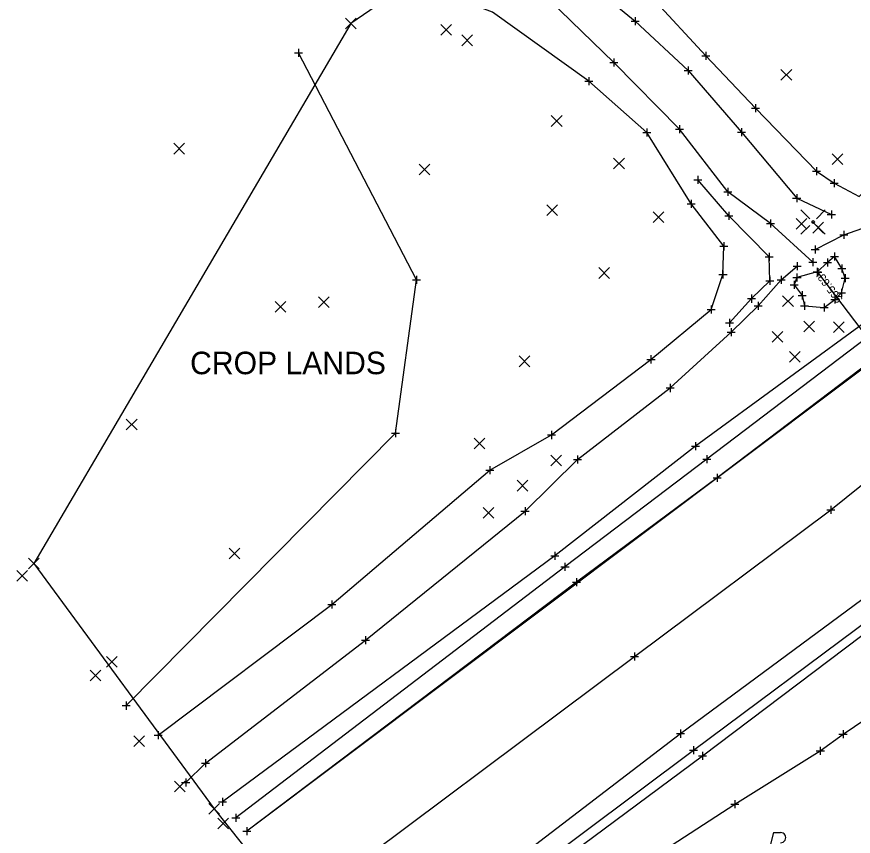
# Model space of a CAD drawing. Extents: x 120332 to 120776, y 463407 to 463745.
# Drawn here: x 120357.5 to 120461.5, y 463500.9 to 463602.7 of the extents above; entities that cross this region are included whole.
import ezdxf

# ---------------------------------------------------------------- set-up
doc = ezdxf.new("R2010")
doc.units = 0
for name, color, linetype in [('Default', 7, 'Continuous'), ('DR_X_Storm_Sewer', 7, 'Continuous'), ('DV_X_Property_Line', 7, 'Continuous'), ('DV_X_Section_VMS_Line', 7, 'Continuous'), ('GE_X_Alignment', 7, 'Continuous'), ('GE_X_Alignment_100_Bearings', 7, 'Continuous'), ('GE_X_Alignment_100_Cardinal_Points', 7, 'Continuous'), ('GE_X_Alignment_100_Distances', 7, 'Continuous'), ('GE_X_Alignment_100_Stations', 7, 'Continuous'), ('RD_X_RR_Cells', 7, 'Continuous'), ('RW_X_Esmt_SH', 7, 'Continuous'), ('SC_Scratch1', 7, 'Continuous'), ('SV_P_Control_Cells_Set', 7, 'Continuous'), ('SV_P_Mon_Cells_Set', 7, 'Continuous'), ('SV_X_Break_Lines', 7, 'Continuous'), ('SV_X_Mon_Cells_Found', 7, 'Continuous'), ('SV_X_Random_Point', 7, 'Continuous'), ('SV_X_Terrain_Boundary', 7, 'Continuous'), ('SV_X_Void_Area', 7, 'Continuous')]:
    doc.layers.add(name, color=color, linetype=linetype)

msp = doc.modelspace()

# ---------------------------------------------------------------- linework, layer by layer
at = {"layer": 'DR_X_Storm_Sewer'}
msp.add_line((120487.84, 463530.38), (120457.07, 463571.01), dxfattribs=at)
at = {"layer": 'DV_X_Property_Line'}
for p, q in [((120456.57, 463571.01), (120457.57, 463571.01)), ((120457.07, 463571.51), (120457.07, 463570.51)), ((120457.07, 463571.01), (120457.07, 463571.01))]:
    msp.add_line(p, q, dxfattribs=at)
at = {"layer": 'DV_X_Section_VMS_Line'}
for p, q in [((120454.98, 463578.73), (120456.07, 463577.64)), ((120456.9, 463577.64), (120458, 463578.73)), ((120454.98, 463575.71), (120456.07, 463576.81)), ((120456.9, 463576.81), (120458, 463575.71))]:
    msp.add_line(p, q, dxfattribs=at)
msp.add_circle((120456.49, 463577.23), 0.17, dxfattribs=at)
at = {"layer": 'GE_X_Alignment'}
for points in [[(120543.45, 463625.61), (120502.74, 463595.17), (120482.09, 463579.11), (120464.32, 463565.8), (120441.86, 463549.38), (120424.38, 463535.76), (120383.06, 463505.19)], [(120400.78, 463479.74), (120442.74, 463510.89), (120464.41, 463527.27), (120481.24, 463539.36), (120504.94, 463557.9), (120520.74, 463569.69), (120562.77, 463600.78)]]:
    msp.add_lwpolyline(points, dxfattribs=at)
at = {"layer": 'GE_X_Alignment_100_Bearings'}
for points in [[(120544.78, 463624.2), (120504.28, 463593.4), (120483.22, 463577.47), (120465.62, 463564.72), (120443.3, 463547.76), (120425.65, 463534.4), (120384.72, 463503.19)], [(120400.11, 463480.54), (120441.64, 463511.61), (120463.87, 463528.17), (120480.16, 463540.69), (120504.52, 463558.73), (120520.21, 463570.42), (120561.99, 463601.9)]]:
    msp.add_lwpolyline(points, dxfattribs=at)
at = {"layer": 'GE_X_Alignment_100_Cardinal_Points'}
for points in [[(120546.27, 463622.13), (120505.75, 463591.54), (120484.55, 463575.45), (120386.09, 463501.54)], [(120392.05, 463491.7), (120434.29, 463523.26), (120458.68, 463541.48), (120471.62, 463551.86), (120496.01, 463569.76), (120511.36, 463581.53), (120553.61, 463612.98)], [(120399.18, 463482.46), (120440.01, 463513.66), (120462.57, 463530.32), (120478.53, 463542.4), (120503.14, 463560.74), (120518.65, 463572.53), (120560.39, 463604.03)]]:
    msp.add_lwpolyline(points, dxfattribs=at)
at = {"layer": 'GE_X_Alignment_100_Distances'}
msp.add_lwpolyline([(120392.05, 463491.7), (120434.29, 463523.26), (120458.68, 463541.48), (120471.62, 463551.86), (120496.01, 463569.76), (120511.36, 463581.53), (120553.61, 463612.98)], dxfattribs=at)
at = {"layer": 'GE_X_Alignment_100_Stations'}
for points in [[(120546.27, 463622.13), (120505.75, 463591.54), (120484.55, 463575.45), (120467.37, 463562.71), (120444.55, 463545.45), (120427.07, 463532.49), (120386.09, 463501.54)], [(120399.18, 463482.46), (120440.01, 463513.66), (120462.57, 463530.32), (120478.53, 463542.4), (120503.14, 463560.74), (120518.65, 463572.53), (120560.39, 463604.03)]]:
    msp.add_lwpolyline(points, dxfattribs=at)
at = {"layer": 'RD_X_RR_Cells'}
for points in [[(120421.56, 463619.93), (120426.3, 463612.62), (120436.47, 463605.12), (120443.17, 463597.87), (120449.32, 463591.39), (120456.91, 463583.55), (120459.12, 463582.05), (120462.23, 463580.42), (120466.75, 463584.83), (120476.93, 463591.15), (120482.16, 463596.63), (120497.16, 463604.58), (120521.1, 463620.25), (120539.56, 463634.42)], [(120375.09, 463513.46), (120396.65, 463529.7), (120416.31, 463546.41), (120423.97, 463550.77), (120436.34, 463560.17), (120443.81, 463566.35), (120445.29, 463570.72), (120445.41, 463574.22), (120441.35, 463579.5), (120435.84, 463588.34), (120428.62, 463594.75), (120416.62, 463603.29), (120414.66, 463604.06), (120407.29, 463609.02)]]:
    msp.add_lwpolyline(points, dxfattribs=at)
at = {"layer": 'RW_X_Esmt_SH'}
for q in [(120449.98, 463495.38), (120452.44, 463501.38)]:
    msp.add_line((120451.59, 463501.38), q, dxfattribs=at)
msp.add_arc((120452.45, 463500.74), 0.638, 268.8767, 91.1233, dxfattribs=at)
at = {"layer": 'SV_P_Control_Cells_Set'}
for p, q in [((120398.35, 463601.22), (120399.69, 463602.56)), ((120398.35, 463602.56), (120399.69, 463601.22)), ((120410.23, 463600.43), (120411.56, 463601.77)), ((120410.23, 463601.77), (120411.56, 463600.43)), ((120412.81, 463599.14), (120414.14, 463600.48)), ((120412.81, 463600.48), (120414.14, 463599.14)), ((120452.5, 463594.84), (120453.84, 463596.17)), ((120452.5, 463596.17), (120453.84, 463594.84)), ((120423.95, 463589.11), (120425.28, 463590.45)), ((120423.95, 463590.45), (120425.28, 463589.11)), ((120377.02, 463585.68), (120378.35, 463587.02)), ((120377.02, 463587.02), (120378.35, 463585.68)), ((120431.7, 463583.82), (120433.03, 463585.15)), ((120431.7, 463585.15), (120433.03, 463583.82)), ((120458.87, 463584.38), (120460.2, 463585.71)), ((120458.87, 463585.71), (120460.2, 463584.38)), ((120407.52, 463583.1), (120408.86, 463584.43)), ((120407.52, 463584.43), (120408.86, 463583.1)), ((120423.4, 463578.04), (120424.73, 463579.37)), ((120423.4, 463579.37), (120424.73, 463578.04)), ((120436.61, 463577.17), (120437.94, 463578.51)), ((120436.61, 463578.51), (120437.94, 463577.17)), ((120454.38, 463576.33), (120455.72, 463577.66)), ((120454.38, 463577.66), (120455.72, 463576.33)), ((120456.46, 463575.86), (120457.79, 463577.2)), ((120456.46, 463577.2), (120457.79, 463575.86)), ((120429.85, 463570.22), (120431.18, 463571.56)), ((120429.85, 463571.56), (120431.18, 463570.22)), ((120395, 463566.6), (120396.34, 463567.93)), ((120395, 463567.93), (120396.34, 463566.6)), ((120452.7, 463566.72), (120454.04, 463568.05)), ((120452.7, 463568.05), (120454.04, 463566.72)), ((120389.61, 463566.02), (120390.95, 463567.36)), ((120389.61, 463567.36), (120390.95, 463566.02)), ((120455.34, 463563.57), (120456.67, 463564.9)), ((120455.34, 463564.9), (120456.67, 463563.57)), ((120459.01, 463563.52), (120460.34, 463564.85)), ((120459.01, 463564.85), (120460.34, 463563.52)), ((120451.42, 463562.3), (120452.75, 463563.63)), ((120451.42, 463563.63), (120452.75, 463562.3)), ((120453.57, 463559.8), (120454.9, 463561.13)), ((120453.57, 463561.13), (120454.9, 463559.8)), ((120419.95, 463559.25), (120421.28, 463560.59)), ((120419.95, 463560.59), (120421.28, 463559.25)), ((120371.12, 463551.39), (120372.45, 463552.73)), ((120371.12, 463552.73), (120372.45, 463551.39)), ((120414.36, 463549.06), (120415.69, 463550.39)), ((120414.36, 463550.39), (120415.69, 463549.06)), ((120423.88, 463546.94), (120425.21, 463548.27)), ((120423.88, 463548.27), (120425.21, 463546.94)), ((120419.71, 463543.8), (120421.05, 463545.14)), ((120419.71, 463545.14), (120421.05, 463543.8)), ((120415.48, 463540.43), (120416.82, 463541.77)), ((120415.48, 463541.77), (120416.82, 463540.43)), ((120383.89, 463535.38), (120385.22, 463536.71)), ((120383.89, 463536.71), (120385.22, 463535.38)), ((120358.97, 463534.13), (120360.3, 463535.47)), ((120358.97, 463535.47), (120360.3, 463534.13)), ((120357.5, 463532.61), (120358.83, 463533.95)), ((120357.5, 463533.95), (120358.83, 463532.61)), ((120368.64, 463521.91), (120369.98, 463523.24)), ((120368.64, 463523.24), (120369.98, 463521.91)), ((120366.61, 463520.22), (120367.94, 463521.56)), ((120366.61, 463521.56), (120367.94, 463520.22)), ((120372.07, 463512.05), (120373.4, 463513.39)), ((120372.07, 463513.39), (120373.4, 463512.05)), ((120377.09, 463506.43), (120378.42, 463507.77)), ((120377.09, 463507.77), (120378.42, 463506.43)), ((120381.38, 463503.64), (120382.72, 463504.98)), ((120381.38, 463504.98), (120382.72, 463503.64)), ((120382.49, 463501.82), (120383.82, 463503.15)), ((120382.49, 463503.15), (120383.82, 463501.82))]:
    msp.add_line(p, q, dxfattribs=at)
at = {"layer": 'SV_P_Mon_Cells_Set'}
msp.add_lwpolyline([(120371.12, 463517.14), (120404.59, 463550.98), (120407.21, 463570.06), (120392.52, 463598.26)], dxfattribs=at)
at = {"layer": 'SV_X_Break_Lines'}
for points in [[(120415.86, 463616.83), (120418.39, 463615.32), (120434.39, 463602.18), (120440.95, 463596.06), (120447.6, 463588.4), (120454.45, 463580.2), (120458.76, 463578.15)], [(120446.1, 463564.72), (120448.82, 463567.71), (120451.12, 463569.92), (120451.04, 463572.89), (120446.01, 463577.99), (120442.16, 463582.48)], [(120404.48, 463476.09), (120417.28, 463484.28), (120427.88, 463492.66), (120446.76, 463504.9), (120457.39, 463511.51), (120460.21, 463513.58), (120464.33, 463516.37), (120471.69, 463517.42), (120474.18, 463519.5), (120472.87, 463523.16), (120471.44, 463528.25), (120473.17, 463531.08), (120477.51, 463533.67), (120480.81, 463534.7), (120483.38, 463533.34), (120485.99, 463535.41), (120486.75, 463538.23), (120491.56, 463542.13), (120495.7, 463547.27)]]:
    msp.add_lwpolyline(points, dxfattribs=at)
at = {"layer": 'SV_X_Mon_Cells_Found'}
for p, q in [((120433.89, 463602.18), (120434.89, 463602.18)), ((120434.39, 463602.68), (120434.39, 463601.68)), ((120434.39, 463602.18), (120434.39, 463602.18)), ((120392.52, 463598.76), (120392.52, 463597.76)), ((120392.02, 463598.26), (120393.02, 463598.26)), ((120392.52, 463598.26), (120392.52, 463598.26)), ((120431.73, 463597.54), (120431.73, 463596.54)), ((120442.67, 463597.87), (120443.67, 463597.87)), ((120443.17, 463598.37), (120443.17, 463597.37)), ((120443.17, 463597.87), (120443.17, 463597.87)), ((120431.23, 463597.04), (120432.23, 463597.04)), ((120431.73, 463597.04), (120431.73, 463597.04)), ((120440.95, 463596.56), (120440.95, 463595.56)), ((120440.45, 463596.06), (120441.45, 463596.06)), ((120440.95, 463596.06), (120440.95, 463596.06)), ((120428.12, 463594.75), (120429.12, 463594.75)), ((120428.62, 463595.25), (120428.62, 463594.25)), ((120428.62, 463594.75), (120428.62, 463594.75)), ((120448.82, 463591.39), (120449.82, 463591.39)), ((120449.32, 463591.89), (120449.32, 463590.89)), ((120449.32, 463591.39), (120449.32, 463591.39)), ((120439.87, 463589.26), (120439.87, 463588.26)), ((120435.34, 463588.34), (120436.34, 463588.34)), ((120435.84, 463588.84), (120435.84, 463587.84)), ((120435.84, 463588.34), (120435.84, 463588.34)), ((120439.37, 463588.76), (120440.37, 463588.76)), ((120439.87, 463588.76), (120439.87, 463588.76)), ((120447.1, 463588.4), (120448.1, 463588.4)), ((120447.6, 463588.9), (120447.6, 463587.9)), ((120447.6, 463588.4), (120447.6, 463588.4)), ((120456.91, 463584.05), (120456.91, 463583.05)), ((120442.16, 463582.98), (120442.16, 463581.98)), ((120456.41, 463583.55), (120457.41, 463583.55)), ((120456.91, 463583.55), (120456.91, 463583.55)), ((120441.66, 463582.48), (120442.66, 463582.48)), ((120442.16, 463582.48), (120442.16, 463582.48)), ((120458.62, 463582.05), (120459.62, 463582.05)), ((120459.12, 463582.55), (120459.12, 463581.55)), ((120459.12, 463582.05), (120459.12, 463582.05)), ((120445.4, 463580.97), (120446.4, 463580.97)), ((120445.9, 463581.47), (120445.9, 463580.47)), ((120445.9, 463580.97), (120445.9, 463580.97)), ((120441.35, 463580), (120441.35, 463579)), ((120453.95, 463580.2), (120454.95, 463580.2)), ((120454.45, 463580.7), (120454.45, 463579.7)), ((120454.45, 463580.2), (120454.45, 463580.2)), ((120440.85, 463579.5), (120441.85, 463579.5)), ((120441.35, 463579.5), (120441.35, 463579.5)), ((120445.51, 463577.99), (120446.51, 463577.99)), ((120446.01, 463578.49), (120446.01, 463577.49)), ((120446.01, 463577.99), (120446.01, 463577.99)), ((120458.26, 463578.15), (120459.26, 463578.15)), ((120458.76, 463578.65), (120458.76, 463577.65)), ((120458.76, 463578.15), (120458.76, 463578.15)), ((120450.69, 463577.05), (120451.69, 463577.05)), ((120451.19, 463577.55), (120451.19, 463576.55)), ((120451.19, 463577.05), (120451.19, 463577.05)), ((120460.31, 463576.15), (120460.31, 463575.15)), ((120445.41, 463574.72), (120445.41, 463573.72)), ((120459.81, 463575.65), (120460.81, 463575.65)), ((120460.31, 463575.65), (120460.31, 463575.65)), ((120444.91, 463574.22), (120445.91, 463574.22)), ((120445.41, 463574.22), (120445.41, 463574.22)), ((120456.26, 463573.83), (120457.26, 463573.83)), ((120456.76, 463574.33), (120456.76, 463573.33)), ((120456.76, 463573.83), (120456.76, 463573.83)), ((120450.54, 463572.89), (120451.54, 463572.89)), ((120451.04, 463573.39), (120451.04, 463572.39)), ((120451.04, 463572.89), (120451.04, 463572.89)), ((120456.47, 463572.74), (120456.47, 463571.74)), ((120458.3, 463572.7), (120458.3, 463571.7)), ((120458.66, 463572.94), (120459.66, 463572.94)), ((120459.16, 463573.44), (120459.16, 463572.44)), ((120459.16, 463572.94), (120459.16, 463572.94)), ((120454.03, 463571.74), (120455.03, 463571.74)), ((120454.53, 463572.24), (120454.53, 463571.24)), ((120454.53, 463571.74), (120454.53, 463571.74)), ((120455.97, 463572.24), (120456.97, 463572.24)), ((120456.47, 463572.24), (120456.47, 463572.24)), ((120456.99, 463571.53), (120456.99, 463570.53)), ((120457.8, 463572.2), (120458.8, 463572.2)), ((120458.3, 463572.2), (120458.3, 463572.2)), ((120460.06, 463571.95), (120460.06, 463570.95)), ((120407.21, 463570.56), (120407.21, 463569.56)), ((120444.79, 463570.72), (120445.79, 463570.72)), ((120445.29, 463571.22), (120445.29, 463570.22)), ((120445.29, 463570.72), (120445.29, 463570.72)), ((120452.54, 463570.54), (120452.54, 463569.54)), ((120454.49, 463570.84), (120454.49, 463569.84)), ((120456.49, 463571.03), (120457.49, 463571.03)), ((120456.99, 463571.03), (120456.99, 463571.03)), ((120459.56, 463571.45), (120460.56, 463571.45)), ((120460.06, 463571.45), (120460.06, 463571.45)), ((120460.49, 463570.75), (120460.49, 463569.75)), ((120406.71, 463570.06), (120407.71, 463570.06)), ((120407.21, 463570.06), (120407.21, 463570.06)), ((120450.62, 463569.92), (120451.62, 463569.92)), ((120451.12, 463570.42), (120451.12, 463569.42)), ((120451.12, 463569.92), (120451.12, 463569.92)), ((120452.04, 463570.04), (120453.04, 463570.04)), ((120452.54, 463570.04), (120452.54, 463570.04)), ((120453.99, 463570.34), (120454.99, 463570.34)), ((120454.14, 463569.91), (120454.14, 463568.91)), ((120454.49, 463570.34), (120454.49, 463570.34)), ((120459.99, 463570.25), (120460.99, 463570.25)), ((120460.49, 463570.25), (120460.49, 463570.25)), ((120453.64, 463569.41), (120454.64, 463569.41)), ((120454.14, 463569.41), (120454.14, 463569.41)), ((120455.14, 463568.62), (120455.14, 463567.62)), ((120459.54, 463568.43), (120460.54, 463568.43)), ((120460.04, 463568.93), (120460.04, 463567.93)), ((120460.04, 463568.43), (120460.04, 463568.43)), ((120448.32, 463567.71), (120449.32, 463567.71)), ((120448.82, 463568.21), (120448.82, 463567.21)), ((120448.82, 463567.71), (120448.82, 463567.71)), ((120454.64, 463568.12), (120455.64, 463568.12)), ((120455.14, 463568.12), (120455.14, 463568.12)), ((120458.69, 463567.62), (120459.69, 463567.62)), ((120459.19, 463568.12), (120459.19, 463567.12)), ((120459.19, 463567.62), (120459.19, 463567.62)), ((120443.31, 463566.35), (120444.31, 463566.35)), ((120443.81, 463566.85), (120443.81, 463565.85)), ((120443.81, 463566.35), (120443.81, 463566.35)), ((120449.16, 463566.82), (120450.16, 463566.82)), ((120449.66, 463567.32), (120449.66, 463566.32)), ((120449.66, 463566.82), (120449.66, 463566.82)), ((120454.94, 463566.83), (120455.94, 463566.83)), ((120455.44, 463567.33), (120455.44, 463566.33)), ((120455.44, 463566.83), (120455.44, 463566.83)), ((120457.36, 463566.62), (120458.36, 463566.62)), ((120457.86, 463567.12), (120457.86, 463566.12)), ((120457.86, 463566.62), (120457.86, 463566.62)), ((120445.6, 463564.72), (120446.6, 463564.72)), ((120446.1, 463565.22), (120446.1, 463564.22)), ((120446.1, 463564.72), (120446.1, 463564.72)), ((120445.79, 463563.53), (120446.79, 463563.53)), ((120446.29, 463564.03), (120446.29, 463563.03)), ((120446.29, 463563.53), (120446.29, 463563.53)), ((120435.84, 463560.17), (120436.84, 463560.17)), ((120436.34, 463560.67), (120436.34, 463559.67)), ((120436.34, 463560.17), (120436.34, 463560.17)), ((120438.73, 463557.11), (120438.73, 463556.11)), ((120438.23, 463556.61), (120439.23, 463556.61)), ((120438.73, 463556.61), (120438.73, 463556.61)), ((120404.09, 463550.98), (120405.09, 463550.98)), ((120404.59, 463551.48), (120404.59, 463550.48)), ((120404.59, 463550.98), (120404.59, 463550.98)), ((120423.47, 463550.77), (120424.47, 463550.77)), ((120423.97, 463551.27), (120423.97, 463550.27)), ((120423.97, 463550.77), (120423.97, 463550.77)), ((120441.86, 463549.88), (120441.86, 463548.88)), ((120441.36, 463549.38), (120442.36, 463549.38)), ((120441.86, 463549.38), (120441.86, 463549.38)), ((120426.7, 463547.74), (120427.7, 463547.74)), ((120427.2, 463548.24), (120427.2, 463547.24)), ((120427.2, 463547.74), (120427.2, 463547.74)), ((120442.8, 463547.76), (120443.8, 463547.76)), ((120443.3, 463548.26), (120443.3, 463547.26)), ((120443.3, 463547.76), (120443.3, 463547.76)), ((120416.31, 463546.91), (120416.31, 463545.91)), ((120415.81, 463546.41), (120416.81, 463546.41)), ((120416.31, 463546.41), (120416.31, 463546.41)), ((120444.55, 463545.95), (120444.55, 463544.95)), ((120444.55, 463545.95), (120444.55, 463544.95)), ((120444.05, 463545.45), (120445.05, 463545.45)), ((120444.05, 463545.45), (120445.05, 463545.45)), ((120444.55, 463545.45), (120444.55, 463545.45)), ((120444.55, 463545.45), (120444.55, 463545.45)), ((120420.68, 463541.79), (120420.68, 463540.79)), ((120458.18, 463541.48), (120459.18, 463541.48)), ((120458.18, 463541.48), (120459.18, 463541.48)), ((120458.68, 463541.98), (120458.68, 463540.98)), ((120458.68, 463541.98), (120458.68, 463540.98)), ((120458.68, 463541.48), (120458.68, 463541.48)), ((120458.68, 463541.48), (120458.68, 463541.48)), ((120420.18, 463541.29), (120421.18, 463541.29)), ((120420.68, 463541.29), (120420.68, 463541.29)), ((120424.38, 463536.26), (120424.38, 463535.26)), ((120423.88, 463535.76), (120424.88, 463535.76)), ((120424.38, 463535.76), (120424.38, 463535.76)), ((120425.15, 463534.4), (120426.15, 463534.4)), ((120425.65, 463534.9), (120425.65, 463533.9)), ((120425.65, 463534.4), (120425.65, 463534.4)), ((120426.57, 463532.49), (120427.57, 463532.49)), ((120426.57, 463532.49), (120427.57, 463532.49)), ((120427.07, 463532.99), (120427.07, 463531.99)), ((120427.07, 463532.99), (120427.07, 463531.99)), ((120427.07, 463532.49), (120427.07, 463532.49)), ((120427.07, 463532.49), (120427.07, 463532.49)), ((120396.65, 463530.2), (120396.65, 463529.2)), ((120396.15, 463529.7), (120397.15, 463529.7)), ((120396.65, 463529.7), (120396.65, 463529.7)), ((120400.84, 463525.78), (120400.84, 463524.78)), ((120400.34, 463525.28), (120401.34, 463525.28)), ((120400.84, 463525.28), (120400.84, 463525.28)), ((120434.29, 463523.76), (120434.29, 463522.76)), ((120434.29, 463523.76), (120434.29, 463522.76)), ((120433.79, 463523.26), (120434.79, 463523.26)), ((120433.79, 463523.26), (120434.79, 463523.26)), ((120434.29, 463523.26), (120434.29, 463523.26)), ((120434.29, 463523.26), (120434.29, 463523.26)), ((120371.12, 463517.64), (120371.12, 463516.64)), ((120370.62, 463517.14), (120371.62, 463517.14)), ((120371.12, 463517.14), (120371.12, 463517.14)), ((120374.59, 463513.46), (120375.59, 463513.46)), ((120375.09, 463513.96), (120375.09, 463512.96)), ((120375.09, 463513.46), (120375.09, 463513.46)), ((120439.51, 463513.66), (120440.51, 463513.66)), ((120439.51, 463513.66), (120440.51, 463513.66)), ((120440.01, 463514.16), (120440.01, 463513.16)), ((120440.01, 463514.16), (120440.01, 463513.16)), ((120440.01, 463513.66), (120440.01, 463513.66)), ((120440.01, 463513.66), (120440.01, 463513.66)), ((120459.71, 463513.58), (120460.71, 463513.58)), ((120460.21, 463514.08), (120460.21, 463513.08)), ((120460.21, 463513.58), (120460.21, 463513.58)), ((120441.14, 463511.61), (120442.14, 463511.61)), ((120441.64, 463512.11), (120441.64, 463511.11)), ((120441.64, 463511.61), (120441.64, 463511.61)), ((120442.74, 463511.39), (120442.74, 463510.39)), ((120456.89, 463511.51), (120457.89, 463511.51)), ((120457.39, 463512.01), (120457.39, 463511.01)), ((120457.39, 463511.51), (120457.39, 463511.51)), ((120380.95, 463510.49), (120380.95, 463509.49)), ((120442.24, 463510.89), (120443.24, 463510.89)), ((120442.74, 463510.89), (120442.74, 463510.89)), ((120380.45, 463509.99), (120381.45, 463509.99)), ((120380.95, 463509.99), (120380.95, 463509.99)), ((120378, 463507.59), (120379, 463507.59)), ((120378.5, 463508.09), (120378.5, 463507.09)), ((120378.5, 463507.59), (120378.5, 463507.59)), ((120382.56, 463505.19), (120383.56, 463505.19)), ((120383.06, 463505.69), (120383.06, 463504.69)), ((120383.06, 463505.19), (120383.06, 463505.19)), ((120446.76, 463505.4), (120446.76, 463504.4)), ((120446.26, 463504.9), (120447.26, 463504.9)), ((120446.76, 463504.9), (120446.76, 463504.9)), ((120384.22, 463503.19), (120385.22, 463503.19)), ((120384.72, 463503.69), (120384.72, 463502.69)), ((120384.72, 463503.19), (120384.72, 463503.19)), ((120386.09, 463502.04), (120386.09, 463501.04)), ((120386.09, 463502.04), (120386.09, 463501.04)), ((120385.59, 463501.54), (120386.59, 463501.54)), ((120385.59, 463501.54), (120386.59, 463501.54)), ((120386.09, 463501.54), (120386.09, 463501.54)), ((120386.09, 463501.54), (120386.09, 463501.54))]:
    msp.add_line(p, q, dxfattribs=at)
at = {"layer": 'SV_X_Random_Point'}
for points in [[(120456.76, 463573.83), (120460.31, 463575.65), (120464.21, 463577), (120470.14, 463581.09), (120477.81, 463589.12), (120484.83, 463592.51), (120498.59, 463602.34), (120522.18, 463618.33), (120540.78, 463632.41)], [(120456.47, 463572.24), (120451.19, 463577.05), (120445.9, 463580.97), (120439.87, 463588.76), (120431.73, 463597.04), (120421.06, 463607.4), (120418.98, 463610.15), (120413.82, 463614.49)], [(120378.5, 463507.59), (120380.95, 463509.99), (120400.84, 463525.28), (120420.68, 463541.29), (120427.2, 463547.74), (120438.73, 463556.61), (120446.29, 463563.53), (120449.66, 463566.82), (120452.54, 463570.04), (120454.53, 463571.74)]]:
    msp.add_lwpolyline(points, dxfattribs=at)
at = {"layer": 'SV_X_Terrain_Boundary'}
msp.add_lwpolyline([(120382.05, 463504.31), (120392.05, 463491.7), (120404.48, 463476.09), (120419.01, 463449.44), (120492.05, 463471.81), (120514.57, 463481.5), (120536.71, 463497.24), (120541.46, 463506.92), (120568.63, 463561.6), (120583.37, 463575.39), (120540.78, 463632.41), (120527.21, 463655.25), (120435.5, 463626.86), (120399.02, 463601.89), (120359.63, 463534.8), (120382.05, 463504.31)], dxfattribs=at)
at = {"layer": 'SV_X_Void_Area'}
msp.add_lwpolyline([(120456.99, 463571.03), (120454.49, 463570.34), (120454.14, 463569.41), (120455.14, 463568.12), (120455.44, 463566.83), (120457.86, 463566.62), (120459.19, 463567.62), (120460.04, 463568.43), (120460.49, 463570.25), (120460.06, 463571.45), (120459.16, 463572.94), (120458.3, 463572.2)], close=True, dxfattribs=at)

# ---------------------------------------------------------------- texts
at = {"layer": 'Default'}
msp.add_text('CROP LANDS', height=2.8, dxfattribs=at).set_placement((120379.05, 463558.32))
at = {"layer": 'SC_Scratch1'}
msp.add_text("965.63'", height=1, rotation=127.1331, dxfattribs=at).set_placement((120460.25, 463567.64))

doc.saveas('drawing.dxf')
